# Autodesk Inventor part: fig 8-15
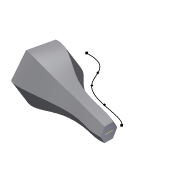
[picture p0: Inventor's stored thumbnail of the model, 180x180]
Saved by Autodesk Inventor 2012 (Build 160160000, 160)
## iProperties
Created: 2004-05
Part Number: fig 8-15
Document SubType Name: Modeling
Designer: CADCIM Technologies
Manufacturer: Standard
Standards Organization: Custom
Density: 1 g/cm^3
Material: Default
Author: CADCIM Technologies
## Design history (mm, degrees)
workplane "Work Plane2"
sketch "Sketch7"
  geometry: L1 (-42.583, 6.068)-(-42.583, 0.37) reference; 5 further points
  constraints: 1 point on line, 5 other
sketch "Sketch8"
  geometry: L1 (-42.583, 3.219)-(-107.269, 18.236); L2 (-42.583, 6.068)-(-42.583, 0.37) reference
  constraints: 2 end point, 1 midpoint
sweep "Sweep7" sketch "Sketch7", "Sketch8" dims "d6" = 0
body "Solid1"
sketch "Sketch2"
  geometry: L1 (-5.697, 0)-(-2.849, 4.934); L2 (-2.849, 4.934)-(2.849, 4.934); L3 (2.849, 4.934)-(5.697, 0); L4 (5.697, 0)-(2.849, -4.934); L5 (2.849, -4.934)-(-2.849, -4.934); L6 (-2.849, -4.934)-(-5.697, 0); 2 further points
  constraints: 12 end point, 1 coincident, 12 other
